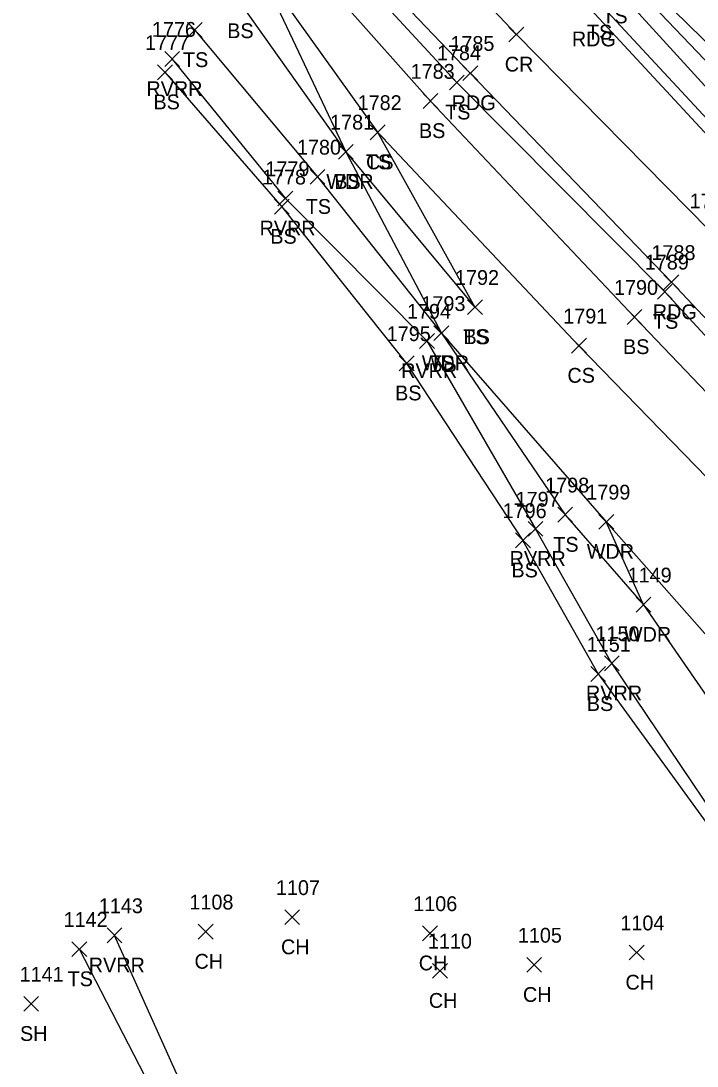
# Model space of a CAD drawing. Extents: x 1469310 to 1475157, y 493997 to 498873.
# Drawn here: x 1469309.9 to 1469401.2, y 498651.4 to 498792.5 of the extents above; entities that cross this region are included whole.
import ezdxf

# ---------------------------------------------------------------- set-up
doc = ezdxf.new("R2010")
doc.units = 0
for name, color, linetype in [('L_A', 7, 'Continuous'), ('L_I', 7, 'Continuous'), ('L_TIC', 7, 'Continuous'), ('LAWA', 7, 'Continuous'), ('LAWE', 7, 'Continuous'), ('LELB', 7, 'Continuous'), ('P_A', 7, 'Continuous'), ('P_I', 7, 'Continuous'), ('P_TIC', 7, 'Continuous'), ('PEU', 7, 'Continuous'), ('PRC', 7, 'Continuous')]:
    doc.layers.add(name, color=color, linetype=linetype)

msp = doc.modelspace()

# ---------------------------------------------------------------- linework, layer by layer
at = {"layer": 'L_TIC'}
for points in [[(1469332.36, 498790.27), (1469334.36, 498792.27)], [(1469334.36, 498790.27), (1469332.36, 498792.27)], [(1469329.31, 498786.36), (1469331.31, 498788.36)], [(1469331.31, 498786.36), (1469329.31, 498788.36)], [(1469328.34, 498784.57), (1469330.34, 498786.57)], [(1469330.34, 498784.57), (1469328.34, 498786.57)], [(1469367.78, 498783.2), (1469369.78, 498785.2)], [(1469369.78, 498783.2), (1469367.78, 498785.2)], [(1469364.22, 498780.69), (1469366.22, 498782.69)], [(1469366.22, 498780.69), (1469364.22, 498782.69)], [(1469357.07, 498776.47), (1469359.07, 498778.47)], [(1469359.07, 498776.47), (1469357.07, 498778.47)], [(1469357.07, 498776.47), (1469359.07, 498778.47)], [(1469359.07, 498776.47), (1469357.07, 498778.47)], [(1469352.78, 498773.83), (1469354.78, 498775.83)], [(1469354.78, 498773.83), (1469352.78, 498775.83)], [(1469352.78, 498773.83), (1469354.78, 498775.83)], [(1469354.78, 498773.83), (1469352.78, 498775.83)], [(1469348.95, 498770.45), (1469350.95, 498772.45)], [(1469350.95, 498770.45), (1469348.95, 498772.45)], [(1469344.61, 498767.54), (1469346.61, 498769.54)], [(1469346.61, 498767.54), (1469344.61, 498769.54)], [(1469344.13, 498766.42), (1469346.13, 498768.42)], [(1469346.13, 498766.42), (1469344.13, 498768.42)], [(1469395.87, 498754.94), (1469397.87, 498756.94)], [(1469397.87, 498754.94), (1469395.87, 498756.94)], [(1469370.22, 498752.86), (1469372.22, 498754.86)], [(1469372.22, 498752.86), (1469370.22, 498754.86)], [(1469370.22, 498752.86), (1469372.22, 498754.86)], [(1469372.22, 498752.86), (1469370.22, 498754.86)], [(1469391.79, 498751.52), (1469393.79, 498753.52)], [(1469393.79, 498751.52), (1469391.79, 498753.52)], [(1469365.68, 498749.34), (1469367.68, 498751.34)], [(1469367.68, 498749.34), (1469365.68, 498751.34)], [(1469365.68, 498749.34), (1469367.68, 498751.34)], [(1469367.68, 498749.34), (1469365.68, 498751.34)], [(1469363.74, 498748.29), (1469365.74, 498750.29)], [(1469365.74, 498748.29), (1469363.74, 498750.29)], [(1469384.28, 498747.65), (1469386.28, 498749.65)], [(1469386.28, 498747.65), (1469384.28, 498749.65)], [(1469360.99, 498745.27), (1469362.99, 498747.27)], [(1469362.99, 498745.27), (1469360.99, 498747.27)], [(1469382.4, 498724.83), (1469384.4, 498726.83)], [(1469384.4, 498724.83), (1469382.4, 498726.83)], [(1469387.97, 498723.88), (1469389.97, 498725.88)], [(1469389.97, 498723.88), (1469387.97, 498725.88)], [(1469378.4, 498722.92), (1469380.4, 498724.92)], [(1469380.4, 498722.92), (1469378.4, 498724.92)], [(1469376.71, 498721.37), (1469378.71, 498723.37)], [(1469378.71, 498721.37), (1469376.71, 498723.37)], [(1469392.99, 498712.68), (1469394.99, 498714.68)], [(1469394.99, 498712.68), (1469392.99, 498714.68)], [(1469388.72, 498704.76), (1469390.72, 498706.76)], [(1469390.72, 498704.76), (1469388.72, 498706.76)], [(1469386.88, 498703.33), (1469388.88, 498705.33)], [(1469388.88, 498703.33), (1469386.88, 498705.33)], [(1469345.53, 498670.48), (1469347.53, 498672.48)], [(1469347.53, 498670.48), (1469345.53, 498672.48)], [(1469321.53, 498668.03), (1469323.53, 498670.03)], [(1469323.53, 498668.03), (1469321.53, 498670.03)], [(1469333.84, 498668.53), (1469335.84, 498670.53)], [(1469335.84, 498668.53), (1469333.84, 498670.53)], [(1469364.14, 498668.31), (1469366.14, 498670.31)], [(1469366.14, 498668.31), (1469364.14, 498670.31)], [(1469316.77, 498666.17), (1469318.77, 498668.17)], [(1469318.77, 498666.17), (1469316.77, 498668.17)], [(1469392.07, 498665.71), (1469394.07, 498667.71)], [(1469394.07, 498665.71), (1469392.07, 498667.71)], [(1469365.5, 498663.25), (1469367.5, 498665.25)], [(1469367.5, 498663.25), (1469365.5, 498665.25)], [(1469378.22, 498664.05), (1469380.22, 498666.05)], [(1469380.22, 498664.05), (1469378.22, 498666.05)], [(1469310.26, 498658.78), (1469312.26, 498660.78)], [(1469312.26, 498658.78), (1469310.26, 498660.78)]]:
    msp.add_lwpolyline(points, dxfattribs=at)
at = {"layer": 'LAWA'}
for points in [[(1469550.26, 498635.87), (1469544.55, 498639.35), (1469529.26, 498656.59), (1469521.27, 498666.89), (1469499.1, 498691), (1469482.91, 498705.54), (1469469.32, 498718.6), (1469451.08, 498739.43), (1469431.27, 498758.58), (1469415.67, 498776.75), (1469392.18, 498799.73), (1469384.54, 498811.21)], [(1469341.76, 498800.26), (1469353.78, 498774.83), (1469366.68, 498750.34), (1469388.97, 498724.88)], [(1469393.99, 498713.68), (1469388.97, 498724.88)], [(1469393.99, 498713.68), (1469413.64, 498685.25), (1469432.29, 498661.26), (1469428.53, 498658.9)]]:
    msp.add_lwpolyline(points, dxfattribs=at)
at = {"layer": 'LAWE'}
for points in [[(1469330.31, 498787.36), (1469345.61, 498768.54), (1469364.74, 498749.29), (1469379.4, 498723.92)], [(1469389.72, 498705.76), (1469379.4, 498723.92)], [(1469389.72, 498705.76), (1469405.14, 498682.89), (1469430.85, 498646.13), (1469451.62, 498613.53), (1469475.38, 498586.01), (1469482.32, 498572.69), (1469484.59, 498569.54), (1469489.26, 498567.84), (1469509.66, 498577.17), (1469522.84, 498580.18), (1469533.51, 498579.28), (1469530.31, 498572.64)], [(1469470.69, 498379.21), (1469458.55, 498419.79), (1469444.89, 498450.98), (1469434.22, 498482.51), (1469416.6, 498512.22), (1469399.07, 498537.07), (1469377.97, 498567.13), (1469359.23, 498600.28), (1469339.95, 498630.27), (1469322.53, 498669.03)]]:
    msp.add_lwpolyline(points, dxfattribs=at)
at = {"layer": 'LELB'}
for points in [[(1469469.32, 498718.6), (1469450.25, 498737.56), (1469430.69, 498757.59), (1469415.11, 498773.82), (1469391.34, 498798.74), (1469366.13, 498825.62)], [(1469596.34, 498559.71), (1469578.35, 498585.4), (1469563.74, 498607.63), (1469555.37, 498620.37), (1469550.82, 498626.65), (1469541.68, 498637.32), (1469517.52, 498662), (1469494.24, 498687.27), (1469477.2, 498705.84), (1469448.36, 498735.3), (1469427.59, 498756.34), (1469413.62, 498771.3), (1469390.02, 498797.18), (1469364.14, 498823.89)], [(1469563.74, 498607.63), (1469555.09, 498616.5), (1469548.65, 498625.25), (1469539.23, 498636.49), (1469516.21, 498660.23), (1469492, 498685.05), (1469474.24, 498704.18), (1469446.06, 498733.49), (1469425.87, 498754.55), (1469411.99, 498769.1), (1469387.95, 498794.99), (1469362.09, 498822.05)], [(1469347.69, 498807), (1469368.78, 498784.2), (1469396.87, 498755.94)], [(1469345.16, 498804.23), (1469365.22, 498781.69), (1469392.79, 498752.52)], [(1469341.76, 498800.26), (1469358.07, 498777.47), (1469371.22, 498753.86)], [(1469339.31, 498795.18), (1469353.78, 498774.83), (1469371.22, 498753.86)], [(1469333.36, 498791.27), (1469349.95, 498771.45), (1469366.68, 498750.34), (1469383.4, 498725.83)], [(1469329.34, 498785.57), (1469345.13, 498767.42), (1469361.99, 498746.27), (1469377.71, 498722.37)], [(1469358.07, 498777.47), (1469385.28, 498748.65)], [(1469416.82, 498734.31), (1469396.87, 498755.94)], [(1469413.42, 498730.94), (1469392.79, 498752.52)], [(1469407.36, 498725.91), (1469385.28, 498748.65)], [(1469383.4, 498725.83), (1469393.99, 498713.68)], [(1469403.96, 498707.9), (1469388.97, 498724.88)], [(1469387.88, 498704.33), (1469377.71, 498722.37)], [(1469387.88, 498704.33), (1469404.11, 498681.98), (1469428.9, 498644.42), (1469449.54, 498612.82), (1469474.41, 498585.16), (1469480.64, 498571.19), (1469484.92, 498567.97), (1469489.16, 498565.96), (1469510.3, 498575.29), (1469522.97, 498578.34), (1469531.66, 498578.29)], [(1469468.33, 498378.85), (1469455.23, 498417.9), (1469441.03, 498450.34), (1469428.48, 498479.32), (1469411.17, 498506.47), (1469396.62, 498534.84), (1469375.95, 498565.74), (1469357.01, 498599.52), (1469337.69, 498628.62), (1469317.77, 498667.17)]]:
    msp.add_lwpolyline(points, dxfattribs=at)
at = {"layer": 'P_TIC'}
for points in [[(1469375.82, 498789.67), (1469377.82, 498791.67)], [(1469377.82, 498789.67), (1469375.82, 498791.67)], [(1469369.59, 498784.46), (1469371.59, 498786.46)], [(1469371.59, 498784.46), (1469369.59, 498786.46)], [(1469396.76, 498756.22), (1469398.76, 498758.22)], [(1469398.76, 498756.22), (1469396.76, 498758.22)]]:
    msp.add_lwpolyline(points, dxfattribs=at)
at = {"layer": 'PEU'}
for points in [[(1469787.29, 498391.19), (1469770.79, 498403.19), (1469744.94, 498420.51), (1469711.23, 498443.77), (1469680.07, 498463.21), (1469651.58, 498483.41), (1469630.63, 498501.52), (1469612.52, 498523.24), (1469599.41, 498542.19), (1469591.57, 498556.6), (1469575.61, 498583.06), (1469557.31, 498607.49), (1469540.09, 498628.65), (1469536.24, 498634.99), (1469514.98, 498658.51), (1469490.83, 498684.27), (1469472.69, 498702.57), (1469444.89, 498732.16), (1469424.97, 498753.74), (1469411.28, 498767.74), (1469386.83, 498794.07), (1469360.47, 498820.44)], [(1469348.6, 498808.45), (1469370.59, 498785.46), (1469397.76, 498757.22)], [(1469418.16, 498735.54), (1469397.76, 498757.22)]]:
    msp.add_lwpolyline(points, dxfattribs=at)
at = {"layer": 'PRC'}
msp.add_lwpolyline([(1469354.16, 498814.68), (1469376.82, 498790.67), (1469402.92, 498764.19)], dxfattribs=at)

# ---------------------------------------------------------------- texts
at = {"layer": 'L_A'}
for s, p in [('TS', (1469388.43, 498792.18)), ('BS', (1469337.75, 498790.18)), ('TS', (1469386.36, 498789.99)), ('TS', (1469331.77, 498786.27)), ('RVRR', (1469326.83, 498782.36)), ('BS', (1469327.78, 498780.57)), ('TS', (1469367.19, 498779.2)), ('BS', (1469363.66, 498776.69)), ('TS', (1469356.47, 498772.47)), ('CS', (1469356.51, 498772.47)), ('WDR', (1469351.14, 498769.83)), ('BS', (1469352.22, 498769.83)), ('TS', (1469348.36, 498766.45)), ('RVRR', (1469342.12, 498763.54)), ('BS', (1469343.57, 498762.42)), ('TS', (1469395.28, 498750.94)), ('TS', (1469369.63, 498748.86)), ('BS', (1469369.67, 498748.86)), ('BS', (1469391.23, 498747.52)), ('WDR', (1469364.04, 498745.34)), ('TS', (1469365.09, 498745.34)), ('RVRR', (1469361.25, 498744.29)), ('CS', (1469383.72, 498743.65)), ('BS', (1469360.43, 498741.27)), ('TS', (1469381.81, 498720.83)), ('WDR', (1469386.33, 498719.88)), ('RVRR', (1469375.91, 498718.92)), ('BS', (1469376.15, 498717.37)), ('WDR', (1469391.35, 498708.68)), ('RVRR', (1469386.23, 498700.76)), ('BS', (1469386.33, 498699.33)), ('CH', (1469345.02, 498666.48)), ('CH', (1469333.33, 498664.53)), ('RVRR', (1469319.04, 498664.03)), ('CH', (1469363.63, 498664.31)), ('TS', (1469316.18, 498662.17)), ('CH', (1469391.56, 498661.71)), ('CH', (1469364.99, 498659.25)), ('CH', (1469377.71, 498660.05)), ('SH', (1469309.75, 498654.78))]:
    msp.add_text(s, height=2, dxfattribs=at).set_placement(p)
at = {"layer": 'L_I'}
for s, p in [('1776', (1469327.57, 498790.36)), ('1777', (1469326.65, 498788.57)), ('1784', (1469366.09, 498787.2)), ('1783', (1469362.53, 498784.69)), ('1782', (1469355.37, 498780.47)), ('1782', (1469355.37, 498780.47)), ('1781', (1469351.65, 498777.83)), ('1781', (1469351.65, 498777.83)), ('1780', (1469347.17, 498774.45)), ('1778', (1469342.44, 498770.42)), ('1779', (1469342.91, 498771.54)), ('1789', (1469394.17, 498758.94)), ('1792', (1469368.53, 498756.86)), ('1792', (1469368.53, 498756.86)), ('1790', (1469390.01, 498755.52)), ('1794', (1469362.04, 498752.29)), ('1793', (1469363.99, 498753.34)), ('1793', (1469363.99, 498753.34)), ('1791', (1469383.15, 498751.65)), ('1795', (1469359.3, 498749.27)), ('1798', (1469380.71, 498728.83)), ('1797', (1469376.71, 498726.92)), ('1799', (1469386.27, 498727.88)), ('1796', (1469374.96, 498725.37)), ('1149', (1469391.85, 498716.68)), ('1150', (1469387.51, 498708.76)), ('1151', (1469386.33, 498707.33)), ('1107', (1469344.33, 498674.48)), ('1143', (1469320.4, 498672.03)), ('1108', (1469332.64, 498672.53)), ('1106', (1469362.88, 498672.31)), ('1142', (1469315.64, 498670.17)), ('1104', (1469390.87, 498669.71)), ('1105', (1469377.02, 498668.05)), ('1110', (1469364.86, 498667.25)), ('1141', (1469309.7, 498662.78))]:
    msp.add_text(s, height=2, dxfattribs=at).set_placement(p)
at = {"layer": 'P_A'}
for s, p in [('RDG', (1469384.32, 498789.07)), ('CR', (1469375.25, 498785.67)), ('RDG', (1469368.08, 498780.46)), ('RDG', (1469395.25, 498752.22))]:
    msp.add_text(s, height=2, dxfattribs=at).set_placement(p)
at = {"layer": 'P_I'}
for s, p in [('1785', (1469367.9, 498788.46)), ('1787', (1469400.23, 498767.19)), ('1788', (1469395.07, 498760.22))]:
    msp.add_text(s, height=2, dxfattribs=at).set_placement(p)

doc.saveas('drawing.dxf')
